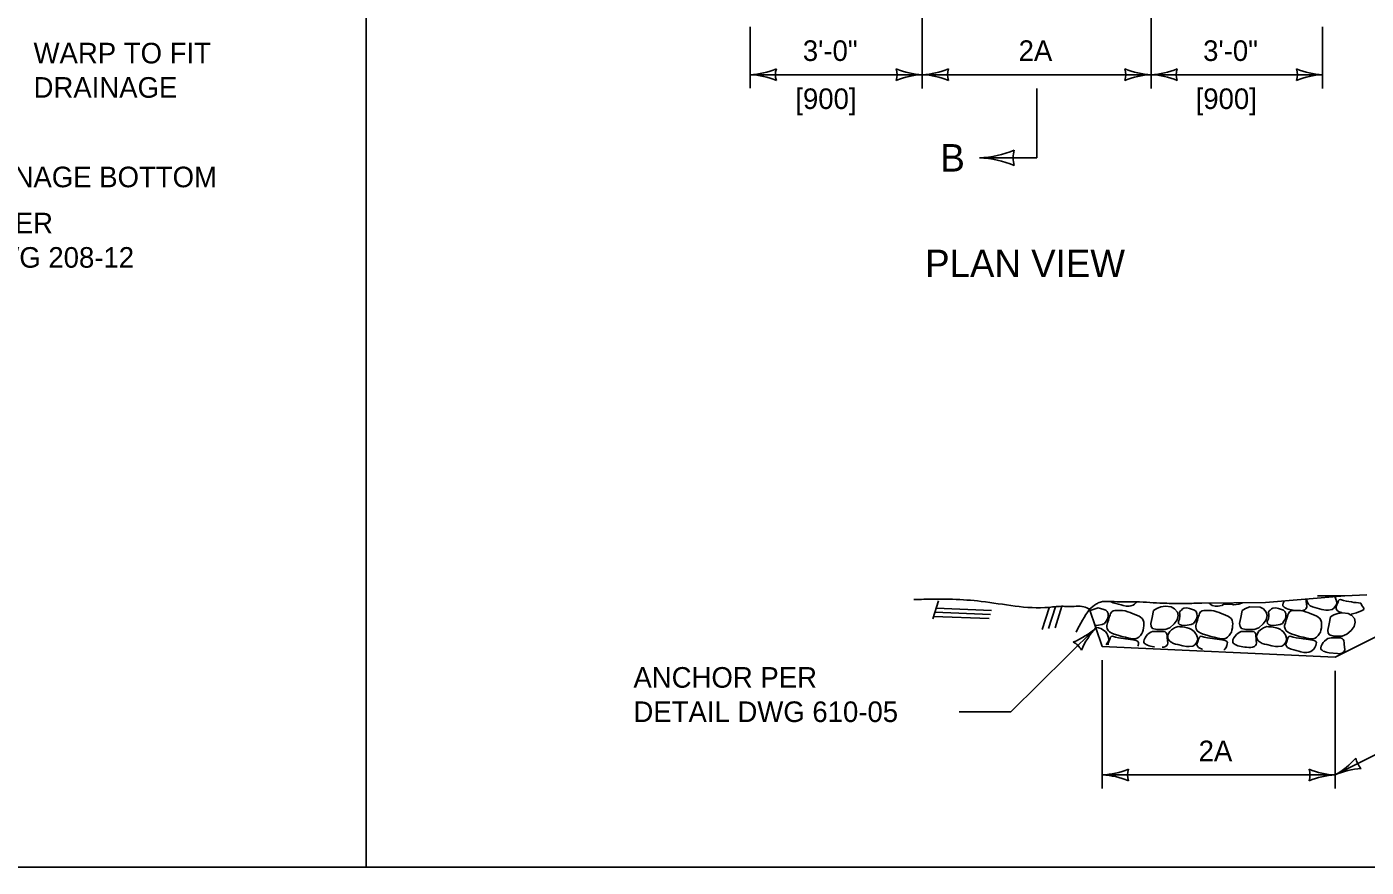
# Model space of a CAD drawing. Extents: x 49991.4 to 50021, y 49987.6 to 50011.4.
# Drawn here: x 50007.078 to 50010.982, y 49990.562 to 49993.01 of the extents above; entities that cross this region are included whole.
import ezdxf

# ---------------------------------------------------------------- set-up
doc = ezdxf.new("R2010")
doc.units = 0
for name, color, linetype in [('Level 1', 7, 'Continuous'), ('Level 2', 7, 'Continuous'), ('Level 3', 7, 'Continuous'), ('Level 6', 7, 'Continuous')]:
    doc.layers.add(name, color=color, linetype=linetype)

msp = doc.modelspace()

# ---------------------------------------------------------------- linework, layer by layer
at = {"layer": 'Level 1'}
for p, q in [((50008.0668, 49990.5622), (50008.0668, 49998.9992)), ((50009.7355, 49991.338), (50009.7192, 49991.2859)), ((50010.0579, 49991.3182), (50010.0382, 49991.255)), ((50010.0763, 49991.3204), (50010.0566, 49991.2572)), ((50010.0948, 49991.3222), (50010.0753, 49991.2597)), ((50009.7214, 49991.293), (50009.8832, 49991.2864)), ((50009.7251, 49991.3049), (50009.8869, 49991.2983)), ((50009.7287, 49991.3164), (50009.8906, 49991.3098)), ((50010.1762, 49991.3139), (50010.2132, 49991.2052)), ((49999.3835, 49990.5622), (50016.7501, 49990.5622))]:
    msp.add_line(p, q, dxfattribs=at)
for points in [[(50015.5568, 49992.9155), (50015.0142, 49992.7795), (50014.842, 49992.7186), (50014.7514, 49992.663), (50013.8692, 49992.663), (50010.8919, 49991.1744), (50010.2132, 49991.2052)], [(50010.8919, 49991.1744), (50013.8692, 49992.663)], [(50010.1927, 49991.2663), (50010.2017, 49991.2675), (50010.2131, 49991.269), (50010.2197, 49991.2724), (50010.2244, 49991.2789), (50010.2287, 49991.2862), (50010.2302, 49991.2935), (50010.23, 49991.3017), (50010.2273, 49991.3069), (50010.2232, 49991.3108), (50010.2172, 49991.3129), (50010.2082, 49991.3155), (50010.2006, 49991.3175), (50010.1774, 49991.3103)], [(50010.3128, 49991.3351), (50010.311, 49991.3327), (50010.3069, 49991.3282), (50010.3028, 49991.3256), (50010.2967, 49991.3237), (50010.2909, 49991.3226), (50010.2827, 49991.3228), (50010.2739, 49991.3245), (50010.2679, 49991.3263), (50010.2603, 49991.3282), (50010.2527, 49991.3308), (50010.2452, 49991.3327), (50010.2386, 49991.3349), (50010.2366, 49991.3362), (50010.2364, 49991.3362)], [(50010.9846, 49991.3557), (50010.92, 49991.353), (50010.6892, 49991.3333), (50010.503, 49991.3318)], [(50010.5601, 49991.325), (50010.5558, 49991.3237), (50010.55, 49991.3226), (50010.5418, 49991.3228), (50010.533, 49991.3245), (50010.5249, 49991.3317), (50010.5239, 49991.3319)], [(50010.6218, 49991.3327), (50010.611, 49991.328), (50010.5952, 49991.3269), (50010.5886, 49991.3282), (50010.5789, 49991.3284), (50010.573, 49991.3289), (50010.5664, 49991.3271), (50010.5612, 49991.325)], [(50010.6212, 49991.3105), (50010.6172, 49991.2901), (50010.6135, 49991.2718), (50010.6148, 49991.2633), (50010.6184, 49991.2577), (50010.6316, 49991.2547), (50010.6558, 49991.2547), (50010.6693, 49991.2595), (50010.6821, 49991.2707), (50010.6903, 49991.2827), (50010.6935, 49991.295), (50010.6911, 49991.3054), (50010.6829, 49991.3151), (50010.6736, 49991.3199)], [(50010.6741, 49991.3199), (50010.6427, 49991.3203), (50010.6308, 49991.3162), (50010.6212, 49991.3105)], [(50010.744, 49991.338), (50010.7433, 49991.3371), (50010.7403, 49991.3315), (50010.7397, 49991.327), (50010.7397, 49991.3238), (50010.7409, 49991.3214), (50010.7436, 49991.3194), (50010.7464, 49991.3173), (50010.7503, 49991.3158), (50010.7548, 49991.314), (50010.7593, 49991.3128), (50010.7639, 49991.3121), (50010.7692, 49991.3106), (50010.7708, 49991.3103)], [(50010.7934, 49991.3093), (50010.7977, 49991.3099), (50010.8031, 49991.3121), (50010.8063, 49991.3147), (50010.8082, 49991.3177), (50010.8092, 49991.321), (50010.8084, 49991.3298), (50010.8078, 49991.336), (50010.8074, 49991.3405), (50010.807, 49991.3434)], [(50010.8099, 49991.3436), (50010.8092, 49991.339), (50010.8108, 49991.3334), (50010.8141, 49991.3283), (50010.8193, 49991.324), (50010.8256, 49991.3207), (50010.8324, 49991.3184), (50010.8392, 49991.3169), (50010.8535, 49991.3134), (50010.8644, 49991.3113), (50010.8722, 49991.3112), (50010.8827, 49991.3125), (50010.8882, 49991.3164), (50010.8923, 49991.3212), (50010.8956, 49991.3272), (50010.8966, 49991.3324), (50010.8952, 49991.3401), (50010.8931, 49991.3455), (50010.8907, 49991.3496), (50010.89, 49991.3505)], [(50010.911, 49991.3039), (50010.9097, 49991.3043), (50010.9032, 49991.3065), (50010.8989, 49991.3089), (50010.896, 49991.3125), (50010.8946, 49991.3162), (50010.895, 49991.3214), (50010.8972, 49991.3263), (50010.8993, 49991.3328), (50010.9015, 49991.3391)], [(50010.9015, 49991.3391), (50010.904, 49991.3412), (50010.9071, 49991.3416), (50010.9159, 49991.339), (50010.9249, 49991.3371), (50010.9319, 49991.336), (50010.9397, 49991.3349), (50010.9459, 49991.3337), (50010.9532, 49991.333), (50010.9666, 49991.3311), (50010.97, 49991.3245), (50010.97, 49991.3245), (50010.9755, 49991.3171), (50010.9751, 49991.3133), (50010.9708, 49991.3096), (50010.9542, 49991.3028), (50010.9388, 49991.2989), (50010.9359, 49991.2958)], [(50010.7677, 49991.3096), (50010.7747, 49991.3097), (50010.7796, 49991.3103), (50010.7901, 49991.3101), (50010.7977, 49991.3086), (50010.8059, 49991.3064), (50010.8124, 49991.3041), (50010.8169, 49991.3023), (50010.8243, 49991.2993), (50010.8313, 49991.2963), (50010.8385, 49991.2937), (50010.8426, 49991.2909), (50010.8475, 49991.287), (50010.8504, 49991.2818), (50010.852, 49991.2756), (50010.8524, 49991.2715), (50010.8522, 49991.2655), (50010.8518, 49991.2596), (50010.8502, 49991.253), (50010.8487, 49991.2467), (50010.8463, 49991.2426), (50010.8424, 49991.237), (50010.8377, 49991.2327), (50010.8334, 49991.2297), (50010.8272, 49991.2278), (50010.8213, 49991.2273), (50010.8091, 49991.2297), (50010.7987, 49991.2325), (50010.7882, 49991.2345), (50010.7767, 49991.2381), (50010.7663, 49991.2413), (50010.7593, 49991.2441), (50010.7527, 49991.2476), (50010.749, 49991.2512), (50010.7457, 49991.2562), (50010.7447, 49991.2624), (50010.7447, 49991.2663), (50010.7468, 49991.2739), (50010.7494, 49991.2819), (50010.7519, 49991.2902), (50010.7544, 49991.2971), (50010.7556, 49991.3015), (50010.7589, 49991.3058), (50010.7634, 49991.309), (50010.7677, 49991.3096)], [(50010.2239, 49991.2103), (50010.2277, 49991.2148), (50010.231, 49991.2207), (50010.232, 49991.226), (50010.2306, 49991.2336), (50010.2285, 49991.239), (50010.2261, 49991.2431), (50010.222, 49991.2487), (50010.2175, 49991.2521), (50010.214, 49991.2549), (50010.2084, 49991.2573), (50010.2017, 49991.2596), (50010.1932, 49991.2616), (50010.1927, 49991.2617)], [(50010.3592, 49991.2487), (50010.3545, 49991.2472), (50010.3502, 49991.2441), (50010.3453, 49991.24), (50010.3412, 49991.2353), (50010.3379, 49991.2306), (50010.3348, 49991.225), (50010.3342, 49991.2206), (50010.3342, 49991.2174), (50010.3354, 49991.215), (50010.3381, 49991.2129), (50010.341, 49991.2109), (50010.3449, 49991.2094), (50010.3494, 49991.2075), (50010.3539, 49991.2064), (50010.3584, 49991.2056), (50010.3637, 49991.2041), (50010.3653, 49991.2038)], [(50010.388, 49991.2028), (50010.3923, 49991.2034), (50010.3976, 49991.2056), (50010.4009, 49991.2082), (50010.4027, 49991.2112), (50010.4037, 49991.2146), (50010.4029, 49991.2234), (50010.4023, 49991.2295), (50010.4019, 49991.234), (50010.4011, 49991.2416), (50010.3992, 49991.2448), (50010.3964, 49991.2476), (50010.3914, 49991.2489), (50010.3855, 49991.2491), (50010.3779, 49991.2493), (50010.3703, 49991.2493), (50010.3646, 49991.2493), (50010.3592, 49991.2487)], [(50010.6826, 49991.2597), (50010.674, 49991.254), (50010.6686, 49991.2485), (50010.6666, 49991.2435), (50010.6637, 49991.2377), (50010.6629, 49991.2325), (50010.6645, 49991.2269), (50010.6678, 49991.2219), (50010.6729, 49991.2176), (50010.6793, 49991.2142), (50010.6861, 49991.212), (50010.6928, 49991.2105), (50010.7072, 49991.2069), (50010.7181, 49991.2049), (50010.7259, 49991.2047), (50010.7363, 49991.206), (50010.7419, 49991.2099), (50010.746, 49991.2148), (50010.7493, 49991.2207), (50010.7503, 49991.226), (50010.7488, 49991.2336), (50010.7468, 49991.239), (50010.7443, 49991.2431), (50010.7402, 49991.2487), (50010.7357, 49991.2521), (50010.7322, 49991.2549), (50010.7267, 49991.2573), (50010.7199, 49991.2596), (50010.7115, 49991.2616), (50010.706, 49991.2627), (50010.698, 49991.2629), (50010.693, 49991.2633), (50010.6875, 49991.2618), (50010.6826, 49991.2597)], [(50010.2132, 49991.2052), (50010.8919, 49991.1744)], [(50010.23, 49991.21), (50010.2304, 49991.215), (50010.2326, 49991.2198), (50010.2347, 49991.2263), (50010.2369, 49991.2327)], [(50010.2369, 49991.2327), (50010.2394, 49991.2347), (50010.2425, 49991.2351), (50010.2513, 49991.2325), (50010.2603, 49991.2306), (50010.2673, 49991.2295), (50010.2751, 49991.2284), (50010.2813, 49991.2273), (50010.2887, 49991.2265), (50010.302, 49991.2247), (50010.3122, 49991.2224), (50010.3159, 49991.2202), (50010.3188, 49991.2165), (50010.3184, 49991.2127), (50010.3174, 49991.2077), (50010.3165, 49991.2061)], [(50010.5056, 49991.1975), (50010.5043, 49991.1978), (50010.4977, 49991.2), (50010.4934, 49991.2025), (50010.4905, 49991.206), (50010.4891, 49991.2097), (50010.4895, 49991.215), (50010.4918, 49991.2198), (50010.4938, 49991.2263), (50010.4961, 49991.2327)], [(50010.4961, 49991.2327), (50010.4985, 49991.2347), (50010.5016, 49991.2351), (50010.5104, 49991.2325), (50010.5195, 49991.2306), (50010.5264, 49991.2295), (50010.5342, 49991.2284), (50010.5404, 49991.2273), (50010.5478, 49991.2265), (50010.5611, 49991.2247), (50010.5714, 49991.2224), (50010.5751, 49991.2202), (50010.5779, 49991.2165), (50010.5775, 49991.2127), (50010.5765, 49991.2077), (50010.5738, 49991.2026), (50010.5701, 49991.1978), (50010.5673, 49991.1947)], [(50010.8752, 49991.2298), (50010.8705, 49991.2283), (50010.8662, 49991.2251), (50010.8613, 49991.221), (50010.8572, 49991.2164), (50010.8539, 49991.2117), (50010.8508, 49991.2061), (50010.8502, 49991.2016), (50010.8502, 49991.1985), (50010.8514, 49991.196), (50010.8541, 49991.194), (50010.857, 49991.1919), (50010.8608, 49991.1904), (50010.8654, 49991.1886), (50010.8699, 49991.1875), (50010.8744, 49991.1867), (50010.8985, 49991.1843), (50010.9045, 49991.1839)], [(50010.904, 49991.1839), (50010.9082, 49991.1845), (50010.9136, 49991.1867), (50010.9169, 49991.1893), (50010.9187, 49991.1923), (50010.9197, 49991.1957), (50010.9189, 49991.2044), (50010.9183, 49991.2106), (50010.9179, 49991.2151), (50010.9171, 49991.2227), (50010.9152, 49991.2259), (50010.9123, 49991.2287), (50010.9074, 49991.23), (50010.9015, 49991.2302), (50010.8939, 49991.2304), (50010.8863, 49991.2304), (50010.8805, 49991.2304), (50010.8752, 49991.2298)]]:
    msp.add_lwpolyline(points, dxfattribs=at)
for points in [[(50010.3621, 49991.3105), (50010.3581, 49991.2901), (50010.3544, 49991.2718), (50010.3556, 49991.2633), (50010.3593, 49991.2577), (50010.3724, 49991.2547), (50010.3967, 49991.2547), (50010.4102, 49991.2595), (50010.4229, 49991.2707), (50010.4311, 49991.2827), (50010.4344, 49991.295), (50010.432, 49991.3054), (50010.4237, 49991.3151), (50010.4135, 49991.3203), (50010.3975, 49991.3226), (50010.3835, 49991.3203), (50010.3716, 49991.3162)], [(50010.4511, 49991.3166), (50010.4472, 49991.3147), (50010.4438, 49991.3114), (50010.4409, 49991.3088), (50010.4386, 49991.3049), (50010.4394, 49991.2983), (50010.439, 49991.2937), (50010.4382, 49991.286), (50010.4349, 49991.2784), (50010.4351, 49991.2726), (50010.4382, 49991.2694), (50010.4435, 49991.2672), (50010.4513, 49991.2662), (50010.4608, 49991.2675), (50010.4723, 49991.269), (50010.4788, 49991.2724), (50010.4836, 49991.2789), (50010.4879, 49991.2862), (50010.4893, 49991.2935), (50010.4891, 49991.3017), (50010.4864, 49991.3069), (50010.4823, 49991.3108), (50010.4764, 49991.3129), (50010.4673, 49991.3155), (50010.4598, 49991.3175)], [(50010.7103, 49991.3166), (50010.7064, 49991.3147), (50010.7029, 49991.3114), (50010.7, 49991.3088), (50010.6977, 49991.3049), (50010.6986, 49991.2983), (50010.6982, 49991.2937), (50010.6973, 49991.286), (50010.6941, 49991.2784), (50010.6943, 49991.2726), (50010.6973, 49991.2694), (50010.7027, 49991.2672), (50010.7105, 49991.2662), (50010.7199, 49991.2675), (50010.7314, 49991.269), (50010.738, 49991.2724), (50010.7427, 49991.2789), (50010.747, 49991.2862), (50010.7484, 49991.2935), (50010.7482, 49991.3017), (50010.7456, 49991.3069), (50010.7415, 49991.3108), (50010.7355, 49991.3129), (50010.7265, 49991.3155), (50010.7189, 49991.3175)], [(50010.2494, 49991.3096), (50010.2564, 49991.3097), (50010.2613, 49991.3103), (50010.2718, 49991.3101), (50010.2794, 49991.3086), (50010.2876, 49991.3064), (50010.2942, 49991.3041), (50010.2987, 49991.3023), (50010.3061, 49991.2993), (50010.3131, 49991.2963), (50010.3202, 49991.2937), (50010.3243, 49991.2909), (50010.3293, 49991.287), (50010.3321, 49991.2818), (50010.3338, 49991.2756), (50010.3342, 49991.2715), (50010.334, 49991.2655), (50010.3336, 49991.2596), (50010.3319, 49991.253), (50010.3305, 49991.2467), (50010.328, 49991.2426), (50010.3241, 49991.237), (50010.3194, 49991.2327), (50010.3151, 49991.2297), (50010.309, 49991.2278), (50010.303, 49991.2273), (50010.2909, 49991.2297), (50010.2804, 49991.2325), (50010.27, 49991.2345), (50010.2585, 49991.2381), (50010.248, 49991.2413), (50010.241, 49991.2441), (50010.2345, 49991.2476), (50010.2308, 49991.2512), (50010.2275, 49991.2562), (50010.2265, 49991.2624), (50010.2265, 49991.2663), (50010.2285, 49991.2739), (50010.2312, 49991.2819), (50010.2336, 49991.2902), (50010.2361, 49991.2971), (50010.2373, 49991.3015), (50010.2406, 49991.3058), (50010.2451, 49991.309)], [(50010.5086, 49991.3096), (50010.5156, 49991.3097), (50010.5205, 49991.3103), (50010.5309, 49991.3101), (50010.5385, 49991.3086), (50010.5467, 49991.3064), (50010.5533, 49991.3041), (50010.5578, 49991.3023), (50010.5652, 49991.2993), (50010.5722, 49991.2963), (50010.5794, 49991.2937), (50010.5835, 49991.2909), (50010.5884, 49991.287), (50010.5913, 49991.2818), (50010.5929, 49991.2756), (50010.5933, 49991.2715), (50010.5931, 49991.2655), (50010.5927, 49991.2596), (50010.5911, 49991.253), (50010.5896, 49991.2467), (50010.5872, 49991.2426), (50010.5833, 49991.237), (50010.5785, 49991.2327), (50010.5742, 49991.2297), (50010.5681, 49991.2278), (50010.5621, 49991.2273), (50010.55, 49991.2297), (50010.5396, 49991.2325), (50010.5291, 49991.2345), (50010.5176, 49991.2381), (50010.5071, 49991.2413), (50010.5002, 49991.2441), (50010.4936, 49991.2476), (50010.4899, 49991.2512), (50010.4866, 49991.2562), (50010.4856, 49991.2624), (50010.4856, 49991.2663), (50010.4876, 49991.2739), (50010.4903, 49991.2819), (50010.4928, 49991.2902), (50010.4952, 49991.2971), (50010.4965, 49991.3015), (50010.4998, 49991.3058), (50010.5043, 49991.309)], [(50010.8781, 49991.2915), (50010.8741, 49991.2712), (50010.8704, 49991.2529), (50010.8716, 49991.2443), (50010.8753, 49991.2387), (50010.8884, 49991.2357), (50010.9127, 49991.2357), (50010.9262, 49991.2406), (50010.9389, 49991.2518), (50010.9471, 49991.2637), (50010.9504, 49991.276), (50010.9479, 49991.2865), (50010.9397, 49991.2962), (50010.9295, 49991.3014), (50010.9135, 49991.3037), (50010.8995, 49991.3014), (50010.8876, 49991.2973)], [(50010.4234, 49991.2597), (50010.4148, 49991.254), (50010.4095, 49991.2485), (50010.4074, 49991.2435), (50010.4046, 49991.2377), (50010.4037, 49991.2325), (50010.4054, 49991.2269), (50010.4087, 49991.2219), (50010.4138, 49991.2176), (50010.4202, 49991.2142), (50010.4269, 49991.212), (50010.4337, 49991.2105), (50010.4481, 49991.2069), (50010.4589, 49991.2049), (50010.4667, 49991.2047), (50010.4772, 49991.206), (50010.4827, 49991.2099), (50010.4868, 49991.2148), (50010.4901, 49991.2207), (50010.4912, 49991.226), (50010.4897, 49991.2336), (50010.4877, 49991.239), (50010.4852, 49991.2431), (50010.4811, 49991.2487), (50010.4766, 49991.2521), (50010.4731, 49991.2549), (50010.4676, 49991.2573), (50010.4608, 49991.2596), (50010.4524, 49991.2616), (50010.4468, 49991.2627), (50010.4388, 49991.2629), (50010.4339, 49991.2633), (50010.4284, 49991.2618)], [(50010.6183, 49991.2487), (50010.6136, 49991.2472), (50010.6093, 49991.2441), (50010.6044, 49991.24), (50010.6003, 49991.2353), (50010.597, 49991.2306), (50010.5939, 49991.225), (50010.5933, 49991.2206), (50010.5933, 49991.2174), (50010.5945, 49991.215), (50010.5972, 49991.2129), (50010.6001, 49991.2109), (50010.604, 49991.2094), (50010.6085, 49991.2075), (50010.613, 49991.2064), (50010.6175, 49991.2056), (50010.6229, 49991.2041), (50010.6288, 49991.203), (50010.6337, 49991.203), (50010.6407, 49991.2026), (50010.6458, 49991.2026), (50010.6514, 49991.2034), (50010.6567, 49991.2056), (50010.66, 49991.2082), (50010.6618, 49991.2112), (50010.6629, 49991.2146), (50010.6621, 49991.2234), (50010.6614, 49991.2295), (50010.661, 49991.234), (50010.6602, 49991.2416), (50010.6584, 49991.2448), (50010.6555, 49991.2476), (50010.6506, 49991.2489), (50010.6446, 49991.2491), (50010.637, 49991.2493), (50010.6294, 49991.2493), (50010.6237, 49991.2493)], [(50010.7552, 49991.2327), (50010.7577, 49991.2347), (50010.7607, 49991.2351), (50010.7696, 49991.2325), (50010.7786, 49991.2306), (50010.7856, 49991.2295), (50010.7934, 49991.2284), (50010.7995, 49991.2273), (50010.8069, 49991.2265), (50010.8202, 49991.2247), (50010.8305, 49991.2224), (50010.8342, 49991.2202), (50010.8371, 49991.2165), (50010.8367, 49991.2127), (50010.8356, 49991.2077), (50010.833, 49991.2026), (50010.8293, 49991.1978), (50010.8252, 49991.1933), (50010.8211, 49991.1907), (50010.8149, 49991.1888), (50010.8092, 49991.1877), (50010.801, 49991.1879), (50010.7921, 49991.1896), (50010.7862, 49991.1915), (50010.7786, 49991.1933), (50010.771, 49991.1959), (50010.7634, 49991.1978), (50010.7568, 49991.2), (50010.7525, 49991.2025), (50010.7497, 49991.206), (50010.7482, 49991.2097), (50010.7486, 49991.215), (50010.7509, 49991.2198), (50010.7529, 49991.2263)]]:
    msp.add_lwpolyline(points, close=True, dxfattribs=at)
msp.add_arc((50010.4822, 49991.0901), 0.3791, 143.8272, 155.5248, dxfattribs=at)
for points in [[(50009.6642, 49991.3419), (50009.6933, 49991.3427), (50009.8602, 49991.3367), (50010.0576, 49991.3192), (50010.0991, 49991.3222), (50010.114, 49991.3214), (50010.1592, 49991.3207), (50010.1762, 49991.3139)], [(50010.503, 49991.3318), (50010.4573, 49991.3305), (50010.4009, 49991.331), (50010.3219, 49991.3348), (50010.3032, 49991.3354), (50010.2846, 49991.3356), (50010.2473, 49991.3358), (50010.234, 49991.3363), (50010.2203, 49991.3365), (50010.2074, 49991.3346), (50010.196, 49991.3292), (50010.1762, 49991.3139)]]:
    msp.add_spline(points, degree=3, dxfattribs=at)
at = {"layer": 'Level 3'}
for p, q in [((50009.6885, 49993.9992), (50009.6885, 49992.8309)), ((50010.3553, 49993.9992), (50010.3553, 49992.8309)), ((50009.1869, 49993.0099), (50009.1869, 49992.8312)), ((50010.8554, 49993.0099), (50010.8554, 49992.8309)), ((50009.6885, 49992.8709), (50009.1869, 49992.8709)), ((50009.6885, 49992.8709), (50010.3553, 49992.8709)), ((50010.3553, 49992.8709), (50010.8554, 49992.8709)), ((50013.0064, 49991.8882), (50010.8919, 49990.831)), ((50010.84, 49991.353), (50010.92, 49991.353)), ((50010.1947, 49991.2595), (50009.9461, 49991.0151)), ((50010.2132, 49991.1652), (50010.2132, 49990.791)), ((50010.8919, 49991.1344), (50010.8919, 49990.791)), ((50009.9461, 49991.0151), (50009.7956, 49991.0151)), ((50010.8919, 49990.831), (50010.2132, 49990.831))]:
    msp.add_line(p, q, dxfattribs=at)
for centre, radius, start, end in [((50009.1754, 49993.1036), 0.233, 272.8273, 292.0772), ((50009.3151, 49992.8709), 0.0548, 162.1388, 197.8612), ((50009.6976, 49993.093), 0.2223, 247.456, 267.6395), ((50009.5602, 49992.8709), 0.0548, 342.1388, 17.8612), ((50009.677, 49993.1036), 0.233, 272.8273, 292.0772), ((50009.8167, 49992.8709), 0.0548, 162.1388, 197.8612), ((50010.3644, 49993.093), 0.2223, 247.456, 267.6395), ((50010.227, 49992.8709), 0.0548, 342.1388, 17.8612), ((50010.3438, 49993.1036), 0.233, 272.8273, 292.0772), ((50010.4835, 49992.8709), 0.0548, 162.1388, 197.8612), ((50010.8645, 49993.093), 0.2223, 247.456, 267.6395), ((50010.7271, 49992.8709), 0.0548, 342.1388, 17.8612), ((50009.1777, 49992.6488), 0.2223, 67.456, 87.6395), ((50009.7, 49992.6382), 0.233, 92.8273, 112.0772), ((50009.6793, 49992.6488), 0.2223, 67.456, 87.6395), ((50010.3668, 49992.6382), 0.233, 92.8273, 112.0772), ((50010.3461, 49992.6488), 0.2223, 67.456, 87.6395), ((50010.8669, 49992.6382), 0.233, 92.8273, 112.0772), ((50010.0261, 49992.6287), 0.073, 162.1388, 197.8612), ((50010.0455, 49991.4244), 0.2223, 291.9687, 312.1522), ((50010.366, 49991.1017), 0.233, 137.34, 156.5898), ((50010.1032, 49991.1697), 0.0548, 26.6515, 62.3738), ((50010.7775, 49991.034), 0.233, 299.3916, 318.6414), ((50010.983, 49990.6282), 0.2223, 94.0203, 114.2038), ((50011.0066, 49990.8883), 0.0548, 188.7031, 224.4255), ((50010.2017, 49991.0637), 0.233, 272.8273, 292.0772), ((50010.204, 49990.6089), 0.2223, 67.456, 87.6395), ((50010.3414, 49990.831), 0.0548, 162.1388, 197.8612), ((50010.901, 49991.0531), 0.2223, 247.456, 267.6395), ((50010.7637, 49990.831), 0.0548, 342.1388, 17.8612), ((50010.9034, 49990.5983), 0.233, 92.8273, 112.0772)]:
    msp.add_arc(centre, radius, start, end, dxfattribs=at)
at = {"layer": 'Level 6'}
for q in [(50010.0219, 49992.8309), (50009.8552, 49992.6287)]:
    msp.add_line((50010.0219, 49992.6287), q, dxfattribs=at)
for centre, radius, start, end in [((50009.8398, 49992.939), 0.3107, 272.8273, 292.0772), ((50009.8429, 49992.3325), 0.2964, 67.456, 87.6395)]:
    msp.add_arc(centre, radius, start, end, dxfattribs=at)

# ---------------------------------------------------------------- texts
at = {"layer": 'Level 2'}
for s, height, p in [('WARP TO FIT', 0.06, (50007.0978, 49992.9038)), ('3\'-0"', 0.06, (50009.3401, 49992.9109)), ('2A', 0.06, (50009.9692, 49992.9109)), ('3\'-0"', 0.06, (50010.507, 49992.9109)), ('DRAINAGE', 0.06, (50007.0978, 49992.8038)), ('[900]', 0.06, (50009.3183, 49992.7709)), ('[900]', 0.06, (50010.4852, 49992.7709)), ('B', 0.08, (50009.7411, 49992.5887)), ('DRAINAGE BOTTOM', 0.06, (50006.8478, 49992.543)), ('ANCHOR PER', 0.06, (50006.6193, 49992.4086)), ('DETAIL DWG 208-12', 0.06, (50006.6193, 49992.3086)), ('PLAN VIEW', 0.08, (50009.6966, 49992.2811)), ('ANCHOR PER', 0.06, (50008.8464, 49991.0851)), ('DETAIL DWG 610-05', 0.06, (50008.8464, 49990.9851)), ('2A', 0.06, (50010.4939, 49990.871))]:
    msp.add_text(s, height=height, dxfattribs=at).set_placement(p)

doc.saveas('drawing.dxf')
